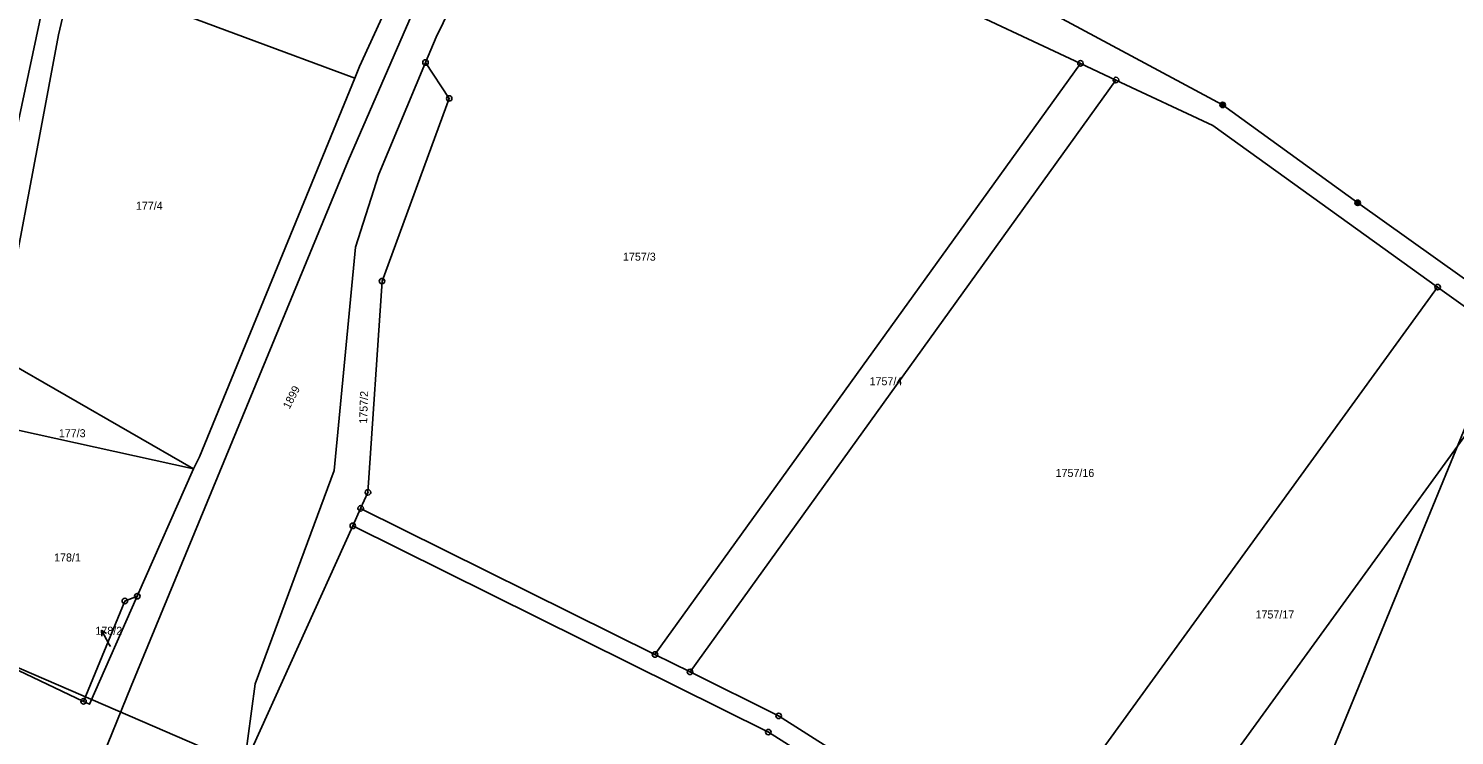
# Model space of a CAD drawing. Extents: x -587171 to -555306, y -1167727 to -1074732.
# Drawn here: x -559864.5 to -559604.4, y -1077320.4 to -1077191.4 of the extents above; entities that cross this region are included whole.
import ezdxf

# ---------------------------------------------------------------- set-up
doc = ezdxf.new("R2010")
doc.units = 0
for name, color, linetype in [('Hranice parcel', 7, 'Continuous'), ('Parcelní čísla', 7, 'Continuous'), ('Pop  PČ popisy', 7, 'Continuous'), ('Poz předměty', 7, 'Continuous'), ('Vnitřní kresba', 7, 'Continuous'), ('Značky bodu BP', 7, 'Continuous')]:
    doc.layers.add(name, color=color, linetype=linetype)

msp = doc.modelspace()

# ---------------------------------------------------------------- linework, layer by layer
at = {"layer": 'Hranice parcel'}
for p, q in [((-559769.65, -1077152.21), (-559672.62, -1077197.74)), ((-559804.99, -1077200.42), (-559856.37, -1077181.34)), ((-559750.22, -1077305.59), (-559672.62, -1077197.74)), ((-559672.62, -1077197.74), (-559666.13, -1077200.78)), ((-559743.82, -1077308.77), (-559666.13, -1077200.78)), ((-559666.13, -1077200.78), (-559648.45, -1077209.08)), ((-559648.45, -1077209.08), (-559607.47, -1077238.56)), ((-559684.16, -1077344.33), (-559607.47, -1077238.56)), ((-559607.47, -1077238.56), (-559591.29, -1077250.2)), ((-559591.29, -1077250.2), (-559667.24, -1077355.04)), ((-559834.36, -1077271.74), (-559869.24, -1077251.62)), ((-559870.59, -1077263.72), (-559834.36, -1077271.74)), ((-559834.36, -1077271.74), (-559844.64, -1077294.96)), ((-559805.34, -1077282.12), (-559803.9, -1077278.93)), ((-559803.9, -1077278.93), (-559750.22, -1077305.59)), ((-559825.15, -1077325.93), (-559805.34, -1077282.12)), ((-559854.44, -1077314.14), (-559875.1, -1077304.36)), ((-559750.22, -1077305.59), (-559743.82, -1077308.77)), ((-559727.66, -1077316.8), (-559743.82, -1077308.77)), ((-559684.16, -1077344.33), (-559727.66, -1077316.8))]:
    msp.add_line(p, q, dxfattribs=at)
for points in [[(-559769.65, -1077152.21), (-559770.77, -1077153.33), (-559790.13, -1077192.93), (-559792.07, -1077197.58)], [(-559794.21, -1077176.64), (-559804.13, -1077198.3), (-559804.99, -1077200.42)], [(-559856.37, -1077181.34), (-559858.99, -1077192.54), (-559862.51, -1077211.37), (-559867.96, -1077240.12), (-559869.24, -1077251.62)], [(-559792.07, -1077197.58), (-559800.59, -1077217.94), (-559804.84, -1077231.29), (-559808.73, -1077272), (-559823.15, -1077310.93), (-559825.15, -1077325.93)], [(-559803.9, -1077278.93), (-559802.57, -1077276.01), (-559800, -1077237.47), (-559787.74, -1077204.14), (-559792.07, -1077197.58)], [(-559804.99, -1077200.42), (-559833.28, -1077269.54), (-559834.36, -1077271.74)], [(-559805.34, -1077282.12), (-559729.54, -1077319.75), (-559649.57, -1077370.38)], [(-559844.64, -1077294.96), (-559846.91, -1077295.84), (-559854.44, -1077314.14)], [(-559844.64, -1077294.96), (-559853.35, -1077314.66), (-559854.44, -1077314.14)]]:
    msp.add_lwpolyline(points, dxfattribs=at)
at = {"layer": 'Pop  PČ popisy'}
for p, q in [((-559849.75, -1077303.79), (-559851.16, -1077301.14)), ((-559851.16, -1077301.14), (-559850.25, -1077301.79)), ((-559851.16, -1077301.14), (-559851.13, -1077302.26)), ((-559849.55, -1077304.16), (-559849.75, -1077303.79))]:
    msp.add_line(p, q, dxfattribs=at)
at = {"layer": 'Poz předměty'}
for p, q in [((-559698, -1077177.75), (-559646.68, -1077205.32)), ((-559806.19, -1077215.54), (-559794.5, -1077188.71)), ((-559646.68, -1077205.32), (-559622.05, -1077223.18)), ((-559845.74, -1077311.35), (-559806.19, -1077215.54)), ((-559622.05, -1077223.18), (-559593.88, -1077243.23)), ((-559593.88, -1077243.23), (-559628.2, -1077326.85)), ((-559898.86, -1077294.03), (-559822.78, -1077326.83)), ((-559845.74, -1077311.35), (-559865.41, -1077359.61))]:
    msp.add_line(p, q, dxfattribs=at)
for centre, radius in [((-559646.68, -1077205.32), 0.5), ((-559646.68, -1077205.32), 0.4), ((-559646.68, -1077205.32), 0.3), ((-559646.68, -1077205.32), 0.2), ((-559646.68, -1077205.32), 0.1), ((-559622.05, -1077223.18), 0.5), ((-559622.05, -1077223.18), 0.4), ((-559622.05, -1077223.18), 0.3), ((-559622.05, -1077223.18), 0.2), ((-559622.05, -1077223.18), 0.1)]:
    msp.add_circle(centre, radius, dxfattribs=at)
at = {"layer": 'Vnitřní kresba'}
msp.add_line((-559861.87, -1077187.38), (-559870.22, -1077226.22), dxfattribs=at)
at = {"layer": 'Značky bodu BP'}
for centre, radius in [((-559792.07, -1077197.58), 0.5), ((-559792.07, -1077197.58), 0.0303), ((-559672.62, -1077197.74), 0.5), ((-559672.62, -1077197.74), 0.0303), ((-559666.13, -1077200.78), 0.5), ((-559666.13, -1077200.78), 0.0303), ((-559787.74, -1077204.14), 0.5), ((-559787.74, -1077204.14), 0.0303), ((-559800, -1077237.47), 0.5), ((-559800, -1077237.47), 0.0303), ((-559607.47, -1077238.56), 0.5), ((-559607.47, -1077238.56), 0.0303), ((-559802.57, -1077276.01), 0.5), ((-559802.57, -1077276.01), 0.0303), ((-559803.9, -1077278.93), 0.5), ((-559803.9, -1077278.93), 0.0303), ((-559805.34, -1077282.12), 0.5), ((-559805.34, -1077282.12), 0.0303), ((-559846.91, -1077295.84), 0.5), ((-559844.64, -1077294.96), 0.5), ((-559844.64, -1077294.96), 0.0303), ((-559846.91, -1077295.84), 0.0303), ((-559750.22, -1077305.59), 0.5), ((-559750.22, -1077305.59), 0.0303), ((-559743.82, -1077308.77), 0.5), ((-559743.82, -1077308.77), 0.0303), ((-559854.44, -1077314.14), 0.5), ((-559854.44, -1077314.14), 0.0303), ((-559727.66, -1077316.8), 0.5), ((-559727.66, -1077316.8), 0.0303), ((-559729.54, -1077319.75), 0.5), ((-559729.54, -1077319.75), 0.0303)]:
    msp.add_circle(centre, radius, dxfattribs=at)

# ---------------------------------------------------------------- texts
at = {"layer": 'Parcelní čísla'}
for s, p in [('177/4', (-559844.89, -1077224.45)), ('1757/3', (-559756.05, -1077233.74)), ('1757/4', (-559711.08, -1077256.47)), ('177/3', (-559858.95, -1077265.95)), ('1757/16', (-559677.15, -1077273.2)), ('178/1', (-559859.81, -1077288.62)), ('1757/17', (-559640.68, -1077299.02)), ('178/2', (-559852.28, -1077301.99))]:
    msp.add_text(s, height=1.46, dxfattribs=at).set_placement(p)
for s, rotation, p in [('1899', 63, (-559816.87, -1077260.92)), ('1757/2', 88, (-559802.73, -1077263.5))]:
    msp.add_text(s, height=1.46, rotation=rotation, dxfattribs=at).set_placement(p)

doc.saveas('drawing.dxf')
